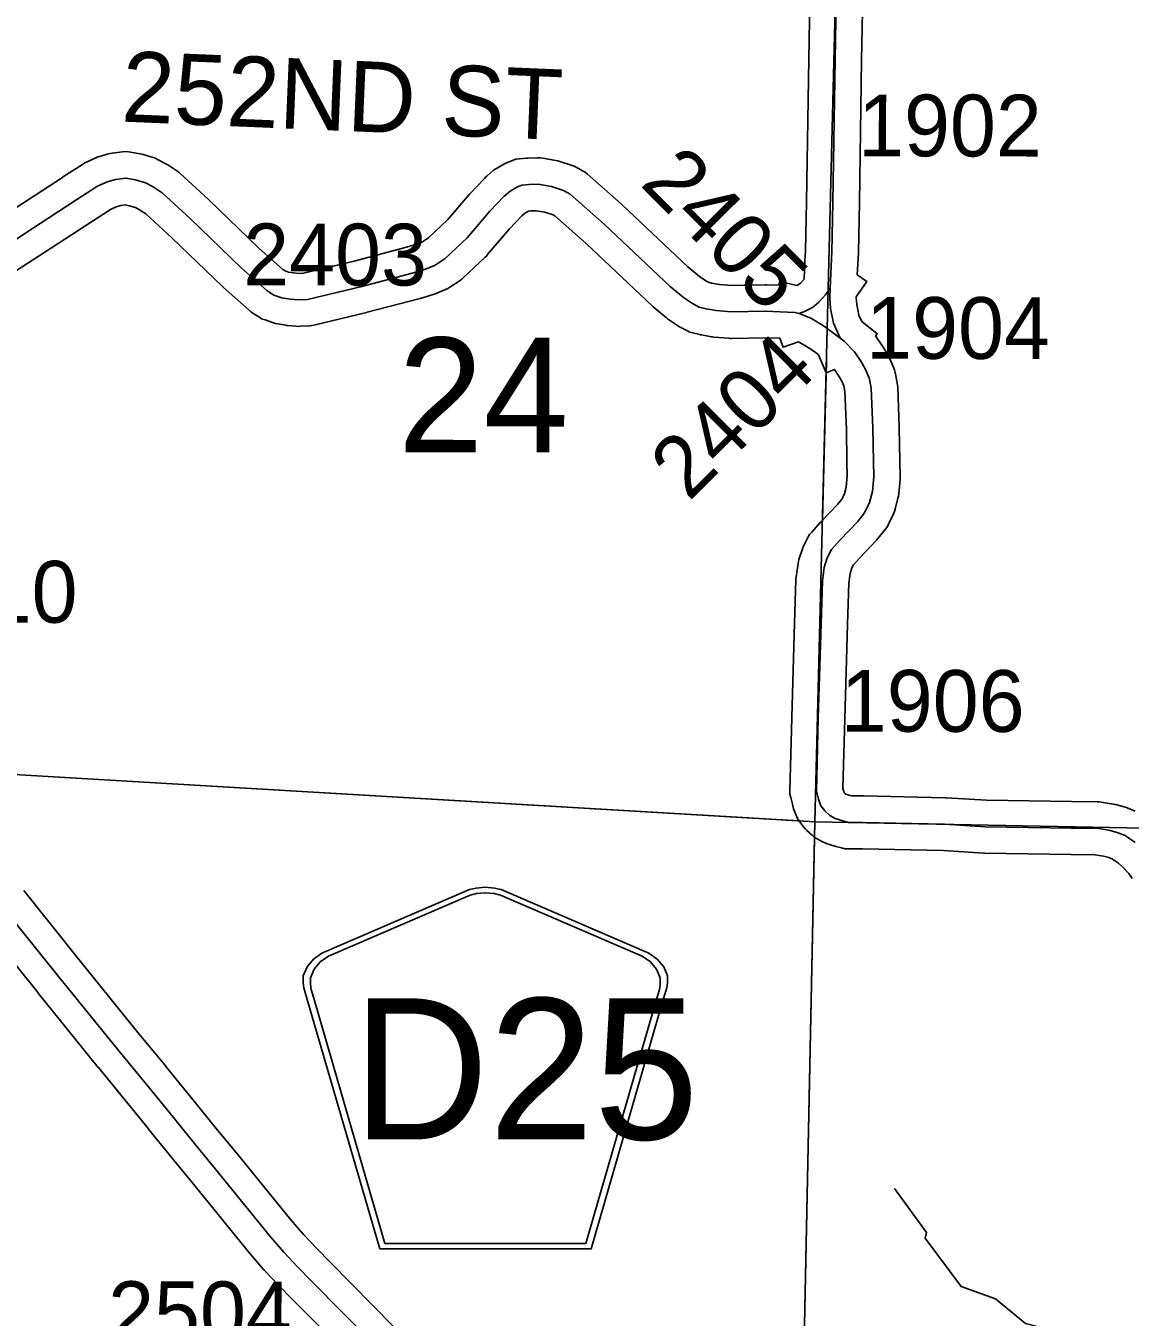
# Model space of a CAD drawing. Extents: x -157.2 to -99.3, y 12.2 to 46.2.
# Drawn here: x -135.784 to -134.532, y 24.227 to 25.691 of the extents above; entities that cross this region are included whole.
import ezdxf

# ---------------------------------------------------------------- set-up
doc = ezdxf.new("R2010")
doc.units = 0
for name, color, linetype in [('tdCoHydroRiver', 7, 'Continuous'), ('tdCoSecRdNmbr', 7, 'Continuous'), ('tdCoSecRdTxt', 7, 'Continuous'), ('tdCoSecRteBand', 7, 'Continuous'), ('tdCoSecRteCL', 7, 'Continuous'), ('tdCoSectLine', 7, 'Continuous'), ('tdCoSectLinePart', 7, 'Continuous'), ('tdCoSectNmbr', 7, 'Continuous'), ('tdCoShieldCoRteHrd', 7, 'Continuous'), ('tdCoSurfAsphalt', 7, 'Continuous'), ('tdCoSurfGravel', 7, 'Continuous'), ('tdCoTwpBndry', 7, 'Continuous'), ('tdCoTwpBndryShd', 7, 'Continuous')]:
    doc.layers.add(name, color=color, linetype=linetype)

msp = doc.modelspace()

# ---------------------------------------------------------------- linework, layer by layer
at = {"layer": 'tdCoHydroRiver'}
msp.add_lwpolyline([(-134.7992, 24.3733), (-134.7629, 24.3232), (-134.7646, 24.317), (-134.7238, 24.262), (-134.6847, 24.2481), (-134.6509, 24.2202), (-134.5538, 24.195), (-134.5234, 24.1561), (-134.4774, 24.1136), (-134.4277, 24.0868), (-134.4029, 24.0695)], dxfattribs=at)
at = {"layer": 'tdCoSecRteBand'}
for points in [[(-135.7948, 25.4851), (-135.7421, 25.5196), (-135.742, 25.5197), (-135.7419, 25.5198), (-135.7184, 25.5348), (-135.7167, 25.5359), (-135.7149, 25.5368), (-135.7043, 25.5417), (-135.7021, 25.5427), (-135.6998, 25.5434), (-135.6902, 25.5461), (-135.688, 25.5467), (-135.6857, 25.547), (-135.6739, 25.5484), (-135.6693, 25.549), (-135.6648, 25.5482), (-135.654, 25.5462), (-135.6523, 25.5459), (-135.6506, 25.5454), (-135.6392, 25.542), (-135.6367, 25.5412), (-135.6343, 25.5399), (-135.6256, 25.5355), (-135.6241, 25.5347), (-135.6227, 25.5338), (-135.6124, 25.5269), (-135.6104, 25.5256), (-135.6087, 25.524), (-135.5771, 25.4949), (-135.5769, 25.4947), (-135.5766, 25.4944), (-135.5191, 25.4391), (-135.4925, 25.4152), (-135.4898, 25.4135), (-135.4861, 25.4122), (-135.4803, 25.4113), (-135.474, 25.4107), (-135.4689, 25.4111), (-135.4116, 25.4247), (-135.3523, 25.4403), (-135.3399, 25.4441), (-135.3341, 25.4465), (-135.3272, 25.4512), (-135.3053, 25.4718), (-135.2807, 25.5007), (-135.2802, 25.5012), (-135.2797, 25.5018), (-135.2639, 25.5185), (-135.2627, 25.5198), (-135.2613, 25.521), (-135.2539, 25.5272), (-135.2518, 25.5289), (-135.2495, 25.5302), (-135.2421, 25.5344), (-135.2405, 25.5353), (-135.2388, 25.536), (-135.2329, 25.5385), (-135.2287, 25.5402), (-135.2242, 25.5407), (-135.2163, 25.5414), (-135.2152, 25.5415), (-135.2142, 25.5415), (-135.2036, 25.5418), (-135.2007, 25.5418), (-135.1979, 25.5414), (-135.1831, 25.5389), (-135.1807, 25.5385), (-135.1784, 25.5377), (-135.1646, 25.533), (-135.1623, 25.5322), (-135.1601, 25.5311), (-135.1527, 25.5271), (-135.1496, 25.5255), (-135.147, 25.5231), (-135.1085, 25.4891), (-135.1081, 25.4888), (-135.1078, 25.4885), (-135.0335, 25.4183), (-135.0202, 25.4072), (-135.0129, 25.4022), (-135.01, 25.4007), (-135.0065, 25.3998), (-134.9975, 25.3983), (-134.9833, 25.397), (-134.946, 25.3977), (-134.9451, 25.3978), (-134.9443, 25.3977), (-134.9303, 25.3972), (-134.9292, 25.4017), (-134.9098, 25.3969), (-134.9084, 25.3976), (-134.9059, 25.3996), (-134.9017, 25.4043), (-134.9007, 25.4254), (-134.9002, 25.4364), (-134.899, 25.4919), (-134.8965, 25.6535), (-134.8965, 25.6536), (-134.8965, 25.6536), (-134.8945, 25.7643)], [(-134.8345, 25.7635), (-134.8365, 25.6526), (-134.839, 25.4908), (-134.839, 25.4907), (-134.839, 25.4906), (-134.8402, 25.4347), (-134.8402, 25.4343), (-134.8402, 25.4339), (-134.8414, 25.4092), (-134.8304, 25.4015), (-134.8426, 25.384), (-134.8426, 25.3831), (-134.8419, 25.3753), (-134.8395, 25.3635), (-134.8363, 25.3561), (-134.8363, 25.3561), (-134.8363, 25.3561), (-134.8188, 25.3422), (-134.8206, 25.3398), (-134.8199, 25.3387), (-134.8127, 25.3283), (-134.8119, 25.3271), (-134.8112, 25.3258), (-134.8062, 25.317), (-134.8055, 25.3157), (-134.805, 25.3145), (-134.8005, 25.3044), (-134.7993, 25.3015), (-134.7986, 25.2984), (-134.7962, 25.2866), (-134.7957, 25.2841), (-134.7956, 25.2816), (-134.7938, 25.2362), (-134.7938, 25.2359), (-134.7938, 25.2357), (-134.7931, 25.1984), (-134.7931, 25.1983), (-134.7931, 25.1983), (-134.7928, 25.1805), (-134.7928, 25.179), (-134.793, 25.1774), (-134.7944, 25.1607), (-134.7947, 25.1582), (-134.7953, 25.1558), (-134.7985, 25.1434), (-134.7992, 25.1406), (-134.8005, 25.138), (-134.8061, 25.1262), (-134.8076, 25.123), (-134.8098, 25.1203), (-134.818, 25.1102), (-134.8187, 25.1093), (-134.8196, 25.1084), (-134.8387, 25.0883), (-134.8457, 25.0804), (-134.8475, 25.077), (-134.8495, 25.0706), (-134.8511, 25.0596), (-134.8525, 25.0125), (-134.8557, 24.9058), (-134.8576, 24.8267), (-134.8568, 24.8233), (-134.8562, 24.8218), (-134.856, 24.8215), (-134.8549, 24.8205), (-134.8547, 24.8204), (-134.8495, 24.8188), (-134.8475, 24.8182), (-134.8352, 24.8182), (-134.8348, 24.8182), (-134.8345, 24.8182), (-134.7418, 24.8162), (-134.7412, 24.8162), (-134.7405, 24.8162), (-134.6951, 24.8133), (-134.5986, 24.8118), (-134.5696, 24.8116), (-134.5673, 24.8115), (-134.565, 24.8112), (-134.5514, 24.809), (-134.55, 24.8087), (-134.5486, 24.8084), (-134.5392, 24.8059), (-134.5374, 24.8054), (-134.5356, 24.8047), (-134.5265, 24.801)], [(-134.53, 24.7247), (-134.5338, 24.7302), (-134.5401, 24.737), (-134.5455, 24.7421), (-134.5521, 24.7466), (-134.5564, 24.7484), (-134.5625, 24.75), (-134.5724, 24.7516), (-134.5992, 24.7518), (-134.5993, 24.7518), (-134.5994, 24.7518), (-134.6968, 24.7533), (-134.6975, 24.7533), (-134.6982, 24.7534), (-134.7437, 24.7563), (-134.8355, 24.7582), (-134.8514, 24.7582), (-134.8554, 24.7582), (-134.8592, 24.7593), (-134.8657, 24.761), (-134.8663, 24.7611), (-134.8668, 24.7613), (-134.8755, 24.764), (-134.8782, 24.7649), (-134.8808, 24.7663), (-134.8867, 24.7695), (-134.8899, 24.7713), (-134.8927, 24.7738), (-134.8986, 24.7792), (-134.9006, 24.7811), (-134.9023, 24.7833), (-134.9068, 24.7892), (-134.9093, 24.7926), (-134.9108, 24.7966), (-134.9135, 24.8037), (-134.9142, 24.8055), (-134.9146, 24.8073), (-134.9168, 24.8164), (-134.9178, 24.8202), (-134.9177, 24.8242), (-134.9157, 24.9073), (-134.9157, 24.9074), (-134.9157, 24.9075), (-134.9125, 25.0143), (-134.9125, 25.0143), (-134.9125, 25.0143), (-134.911, 25.0631), (-134.911, 25.0649), (-134.9107, 25.0666), (-134.9085, 25.0816), (-134.9082, 25.0839), (-134.9075, 25.0862), (-134.904, 25.0973), (-134.9032, 25.0997), (-134.9021, 25.1021), (-134.8974, 25.1112), (-134.8956, 25.1146), (-134.8931, 25.1174), (-134.8832, 25.1285), (-134.8829, 25.1289), (-134.8825, 25.1293), (-134.8639, 25.1488), (-134.8587, 25.1552), (-134.8558, 25.1613), (-134.854, 25.1684), (-134.8529, 25.1812), (-134.8531, 25.1973), (-134.8538, 25.2342), (-134.8554, 25.2768), (-134.8567, 25.2831), (-134.8594, 25.2891), (-134.8629, 25.2954), (-134.8674, 25.3019), (-134.8767, 25.2979), (-134.8855, 25.3185), (-134.8863, 25.3191), (-134.8952, 25.3255), (-134.9072, 25.3329), (-134.908, 25.3332), (-134.9255, 25.327), (-134.9291, 25.3371), (-134.9457, 25.3377), (-134.9838, 25.337), (-134.9854, 25.337), (-134.987, 25.3371), (-135.004, 25.3386), (-135.0053, 25.3387), (-135.0065, 25.3389), (-135.0179, 25.3409), (-135.0189, 25.3411), (-135.02, 25.3414), (-135.0279, 25.3433), (-135.0313, 25.3442), (-135.0344, 25.3458), (-135.042, 25.3497), (-135.0437, 25.3506), (-135.0452, 25.3516), (-135.0553, 25.3585), (-135.0565, 25.3593), (-135.0576, 25.3603), (-135.0727, 25.3729), (-135.0733, 25.3734), (-135.074, 25.3741), (-135.1486, 25.4445), (-135.1841, 25.4759), (-135.1862, 25.477), (-135.1954, 25.4801), (-135.205, 25.4817), (-135.2117, 25.4816), (-135.214, 25.4813), (-135.2141, 25.4813), (-135.2175, 25.4794), (-135.2215, 25.4761), (-135.2355, 25.4612), (-135.2607, 25.4316), (-135.2617, 25.4304), (-135.2629, 25.4293), (-135.2879, 25.4058), (-135.2896, 25.4042), (-135.2916, 25.4028), (-135.303, 25.3952), (-135.3054, 25.3935), (-135.308, 25.3924), (-135.3179, 25.3882), (-135.3193, 25.3876), (-135.3209, 25.3871), (-135.3354, 25.3827), (-135.336, 25.3825), (-135.3366, 25.3824), (-135.3967, 25.3666), (-135.397, 25.3665), (-135.3974, 25.3664), (-135.4573, 25.3521), (-135.4597, 25.3516), (-135.4621, 25.3514), (-135.4722, 25.3507), (-135.4748, 25.3505), (-135.4774, 25.3507), (-135.4872, 25.3517), (-135.4881, 25.3518), (-135.489, 25.352), (-135.4982, 25.3534), (-135.5007, 25.3538), (-135.5031, 25.3547), (-135.5124, 25.3579), (-135.5157, 25.359), (-135.5186, 25.3608), (-135.5265, 25.3657), (-135.5287, 25.3671), (-135.5307, 25.3689), (-135.5595, 25.3947), (-135.5599, 25.3951), (-135.5603, 25.3955), (-135.618, 25.451), (-135.6476, 25.4783), (-135.6546, 25.4829), (-135.6593, 25.4853), (-135.6664, 25.4875), (-135.671, 25.4883), (-135.676, 25.4877), (-135.6812, 25.4863), (-135.6877, 25.4832), (-135.7093, 25.4693), (-135.762, 25.4349), (-135.762, 25.4349), (-135.762, 25.4349), (-135.8081, 25.4048)], [(-135.786, 24.711), (-135.723, 24.6324), (-135.655, 24.5483), (-135.6251, 24.5119), (-135.625, 24.5118), (-135.6249, 24.5116), (-135.598, 24.4784), (-135.5663, 24.4393), (-135.5454, 24.414), (-135.5453, 24.4139), (-135.5453, 24.4138), (-135.4834, 24.3377), (-135.4691, 24.3211), (-135.454, 24.3052), (-135.4389, 24.2896), (-135.3664, 24.2164)], [(-135.4086, 24.1738), (-135.4816, 24.2475), (-135.4817, 24.2476), (-135.4818, 24.2478), (-135.4971, 24.2635), (-135.4972, 24.2636), (-135.4973, 24.2637), (-135.5131, 24.2802), (-135.5136, 24.2808), (-135.5141, 24.2814), (-135.5292, 24.2989), (-135.5294, 24.2992), (-135.5297, 24.2995), (-135.5918, 24.3759), (-135.6126, 24.4012), (-135.6127, 24.4013), (-135.6128, 24.4014), (-135.6446, 24.4406), (-135.6446, 24.4406), (-135.6447, 24.4407), (-135.6714, 24.4738), (-135.7014, 24.5102), (-135.7015, 24.5103), (-135.7016, 24.5105), (-135.7697, 24.5948), (-135.7697, 24.5948), (-135.7697, 24.5949), (-135.8329, 24.6735)]]:
    msp.add_lwpolyline(points, dxfattribs=at)
at = {"layer": 'tdCoSecRteCL'}
for points in [[(-134.8721, 25.394), (-134.8702, 25.4353), (-134.869, 25.4913), (-134.8665, 25.6531), (-134.8645, 25.7641), (-134.8645, 25.8023), (-134.8601, 25.9056), (-134.8591, 25.969), (-134.8564, 26.0654), (-134.851, 26.2222), (-134.8453, 26.3507), (-134.8426, 26.4437), (-134.8404, 26.528), (-134.8342, 26.6669), (-134.831, 26.7672)], [(-135.826, 25.4289), (-135.7784, 25.46), (-135.7257, 25.4945), (-135.7022, 25.5096), (-135.6916, 25.5145), (-135.682, 25.5172), (-135.6702, 25.5187), (-135.6593, 25.5167), (-135.648, 25.5133), (-135.6394, 25.5088), (-135.629, 25.5019), (-135.5974, 25.4728), (-135.5395, 25.4171), (-135.5106, 25.3912), (-135.5027, 25.3862), (-135.4934, 25.383), (-135.4842, 25.3816), (-135.4744, 25.3806), (-135.4643, 25.3813), (-135.4043, 25.3956), (-135.3442, 25.4114), (-135.3296, 25.4158), (-135.3197, 25.42), (-135.3084, 25.4277), (-135.2835, 25.4511), (-135.2579, 25.4812), (-135.2421, 25.498), (-135.2347, 25.5041), (-135.2273, 25.5083), (-135.2214, 25.5108), (-135.2135, 25.5115), (-135.2029, 25.5118), (-135.1881, 25.5093), (-135.1743, 25.5046), (-135.1669, 25.5007), (-135.1284, 25.4666), (-135.0534, 25.3959), (-135.0384, 25.3833), (-135.0283, 25.3764), (-135.0206, 25.3724), (-135.0127, 25.3705), (-135.0014, 25.3685), (-134.9844, 25.367), (-134.9454, 25.3678), (-134.9121, 25.3665), (-134.9074, 25.3653)], [(-134.9074, 25.3653), (-134.9013, 25.3675), (-134.8921, 25.3722), (-134.8852, 25.3776), (-134.8774, 25.3865), (-134.8721, 25.394)], [(-134.8609, 25.3373), (-134.8682, 25.3544), (-134.8717, 25.371), (-134.8727, 25.3825), (-134.8721, 25.394)], [(-134.9074, 25.3653), (-134.9062, 25.365), (-134.8934, 25.3596), (-134.8786, 25.3505), (-134.8682, 25.3431), (-134.8609, 25.3373)], [(-134.5267, 24.7655), (-134.5378, 24.7732), (-134.5469, 24.7769), (-134.5563, 24.7793), (-134.5698, 24.7816), (-134.5989, 24.7818), (-134.6963, 24.7833), (-134.7424, 24.7863), (-134.8352, 24.7882), (-134.8514, 24.7882), (-134.8579, 24.79), (-134.8665, 24.7927), (-134.8724, 24.7959), (-134.8783, 24.8013), (-134.8828, 24.8072), (-134.8855, 24.8144), (-134.8877, 24.8235), (-134.8857, 24.9066), (-134.8825, 25.0134), (-134.881, 25.0622), (-134.8788, 25.0773), (-134.8754, 25.0883), (-134.8707, 25.0975), (-134.8608, 25.1086), (-134.8413, 25.129), (-134.8332, 25.1391), (-134.8275, 25.151), (-134.8243, 25.1633), (-134.8228, 25.1801), (-134.8231, 25.1978), (-134.8238, 25.2351), (-134.8255, 25.2805), (-134.828, 25.2923), (-134.8325, 25.3024), (-134.8374, 25.3113), (-134.8445, 25.3216), (-134.8564, 25.3337), (-134.8609, 25.3373)], [(-135.3873, 24.1949), (-135.4603, 24.2686), (-135.4756, 24.2844), (-135.4914, 24.3009), (-135.5064, 24.3184), (-135.5685, 24.3949), (-135.5895, 24.4203), (-135.6213, 24.4595), (-135.6482, 24.4928), (-135.6783, 24.5293), (-135.7464, 24.6136), (-135.8095, 24.6923)]]:
    msp.add_lwpolyline(points, dxfattribs=at)
at = {"layer": 'tdCoSectLine'}
for points in [[(-134.8895, 24.789), (-134.8649, 25.7715)], [(-135.861, 24.8463), (-134.8895, 24.789)], [(-134.9097, 23.8132), (-134.8895, 24.789)], [(-134.8895, 24.789), (-134.3976, 24.7796), (-134.3771, 24.7791), (-133.9368, 24.7668)]]:
    msp.add_lwpolyline(points, dxfattribs=at)
at = {"layer": 'tdCoSectLinePart'}
for points in [[(-134.8809, 25.1314), (-134.8764, 25.3106)], [(-135.861, 24.8463), (-134.9072, 24.79)], [(-134.9097, 23.8132), (-134.8898, 24.7715)]]:
    msp.add_lwpolyline(points, dxfattribs=at)
at = {"layer": 'tdCoShieldCoRteHrd'}
for points in [[(-135.3826, 24.3046), (-135.4646, 24.5875), (-135.4684, 24.6006), (-135.4692, 24.6065), (-135.4692, 24.6143), (-135.4649, 24.6246), (-135.4577, 24.6331), (-135.4481, 24.6398), (-135.2808, 24.7122), (-135.2733, 24.7138), (-135.2629, 24.7147), (-135.2524, 24.7138), (-135.2449, 24.7122), (-135.0776, 24.6398), (-135.0681, 24.6331), (-135.0608, 24.6246), (-135.0566, 24.6143), (-135.0566, 24.6065), (-135.0573, 24.6006), (-135.0612, 24.5875), (-135.1431, 24.3046)], [(-135.3768, 24.3109), (-135.4565, 24.5862), (-135.4602, 24.5988), (-135.4609, 24.6045), (-135.4609, 24.612), (-135.4568, 24.6219), (-135.4499, 24.63), (-135.4407, 24.6364), (-135.2801, 24.7059), (-135.2729, 24.7075), (-135.2629, 24.7083), (-135.2529, 24.7075), (-135.2456, 24.7059), (-135.0851, 24.6364), (-135.0759, 24.63), (-135.0689, 24.6219), (-135.0648, 24.612), (-135.0648, 24.6045), (-135.0655, 24.5988), (-135.0692, 24.5862), (-135.149, 24.3109)]]:
    msp.add_lwpolyline(points, close=True, dxfattribs=at)
at = {"layer": 'tdCoSurfAsphalt'}
msp.add_lwpolyline([(-135.3873, 24.1949), (-135.4603, 24.2686), (-135.4756, 24.2844), (-135.4914, 24.3009), (-135.5064, 24.3184), (-135.5685, 24.3949), (-135.5895, 24.4203), (-135.6213, 24.4595), (-135.6482, 24.4928), (-135.6783, 24.5293), (-135.7464, 24.6136), (-135.8095, 24.6923)], dxfattribs=at)
at = {"layer": 'tdCoSurfGravel'}
for points in [[(-134.5267, 24.7655), (-134.5378, 24.7732), (-134.5469, 24.7769), (-134.5563, 24.7793), (-134.5698, 24.7816), (-134.5989, 24.7818), (-134.6963, 24.7833), (-134.7424, 24.7863), (-134.8352, 24.7882), (-134.8514, 24.7882), (-134.8579, 24.79), (-134.8665, 24.7927), (-134.8724, 24.7959), (-134.8783, 24.8013), (-134.8828, 24.8072), (-134.8855, 24.8144), (-134.8877, 24.8235), (-134.8857, 24.9066), (-134.8825, 25.0134), (-134.881, 25.0622), (-134.8788, 25.0773), (-134.8754, 25.0883), (-134.8707, 25.0975), (-134.8608, 25.1086), (-134.8413, 25.129), (-134.8332, 25.1391), (-134.8275, 25.151), (-134.8243, 25.1633), (-134.8228, 25.1801), (-134.8231, 25.1978), (-134.8238, 25.2351), (-134.8255, 25.2805), (-134.828, 25.2923), (-134.8325, 25.3024), (-134.8374, 25.3113), (-134.8445, 25.3216), (-134.8564, 25.3337), (-134.8609, 25.3373), (-134.8682, 25.3544), (-134.8717, 25.371), (-134.8727, 25.3825), (-134.8721, 25.394), (-134.8702, 25.4353), (-134.869, 25.4913), (-134.8665, 25.6531), (-134.8645, 25.7641)], [(-135.826, 25.4289), (-135.7784, 25.46), (-135.7257, 25.4945), (-135.7022, 25.5096), (-135.6916, 25.5145), (-135.682, 25.5172), (-135.6702, 25.5187), (-135.6593, 25.5167), (-135.648, 25.5133), (-135.6394, 25.5088), (-135.629, 25.5019), (-135.5974, 25.4728), (-135.5395, 25.4171), (-135.5106, 25.3912), (-135.5027, 25.3862), (-135.4934, 25.383), (-135.4842, 25.3816), (-135.4744, 25.3806), (-135.4643, 25.3813), (-135.4043, 25.3956), (-135.3442, 25.4114), (-135.3296, 25.4158), (-135.3197, 25.42), (-135.3084, 25.4277), (-135.2835, 25.4511), (-135.2579, 25.4812), (-135.2421, 25.498), (-135.2347, 25.5041), (-135.2273, 25.5083), (-135.2214, 25.5108), (-135.2135, 25.5115), (-135.2029, 25.5118), (-135.1881, 25.5093), (-135.1743, 25.5046), (-135.1669, 25.5007), (-135.1284, 25.4666), (-135.0534, 25.3959), (-135.0384, 25.3833), (-135.0283, 25.3764), (-135.0206, 25.3724), (-135.0127, 25.3705), (-135.0014, 25.3685), (-134.9844, 25.367), (-134.9454, 25.3678), (-134.9121, 25.3665), (-134.9074, 25.3653), (-134.9074, 25.3653)], [(-134.9074, 25.3653), (-134.9013, 25.3675), (-134.8921, 25.3722), (-134.8852, 25.3776), (-134.8774, 25.3865), (-134.8721, 25.394)], [(-134.9074, 25.3653), (-134.9062, 25.365), (-134.8934, 25.3596), (-134.8786, 25.3505), (-134.8682, 25.3431), (-134.8609, 25.3373)]]:
    msp.add_lwpolyline(points, dxfattribs=at)
at = {"layer": 'tdCoTwpBndry'}
for points in [[(-134.8809, 25.1315), (-134.8767, 25.2981)], [(-134.9115, 23.735), (-134.9097, 23.8132), (-134.8899, 24.7701)]]:
    msp.add_lwpolyline(points, dxfattribs=at)
at = {"layer": 'tdCoTwpBndryShd'}
msp.add_lwpolyline([(-134.5827, 34.8376), (-134.6206, 33.6622), (-134.6624, 32.6731), (-134.702, 31.6829), (-134.7248, 30.6831), (-134.7505, 29.6994), (-134.7778, 28.6994), (-134.8012, 27.7577), (-134.8314, 26.7672), (-134.8649, 25.7715), (-134.8895, 24.789), (-134.9097, 23.8132), (-134.9318, 22.8156), (-134.9713, 21.779), (-134.9998, 20.7866), (-135.0355, 19.7869), (-135.0694, 18.8043), (-135.1107, 17.815), (-135.1553, 16.8138)], dxfattribs=at)

# ---------------------------------------------------------------- texts
at = {"layer": 'tdCoSecRdNmbr'}
for s, rotation, p in [('1902', 359.8976, (-134.8406, 25.5436)), ('2405', 314.8978, (-135.0889, 25.5112)), ('2403', 359.8971, (-135.5373, 25.3973)), ('1904', 359.8977, (-134.8314, 25.314)), ('2404', 44.8978, (-135.0323, 25.1512)), ('2310', 359.8967, (-135.9333, 25.015)), ('1906', 359.8977, (-134.8601, 24.8912)), ('2504', 359.8972, (-135.6904, 24.1979))]:
    msp.add_text(s, height=0.07, rotation=rotation, dxfattribs=at).set_placement(p)
at = {"layer": 'tdCoSecRdTxt'}
msp.add_text('252ND ST', height=0.08, rotation=357.5857, dxfattribs=at).set_placement((-135.6761, 25.5829))
at = {"layer": 'tdCoSectNmbr'}
msp.add_text('24', height=0.13, rotation=359.8972, dxfattribs=at).set_placement((-135.3619, 25.208))
at = {"layer": 'tdCoShieldCoRteHrd'}
msp.add_text('D25', height=0.16, dxfattribs=at).set_placement((-135.4135, 24.4288))

doc.saveas('drawing.dxf')
